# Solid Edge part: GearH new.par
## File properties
Author: vinurabandara
Template: iso metric part.par
Last saved by: Nimesh.N
Revision: 27
Application: Solid Edge
Density: 7250.000 kg/m^3
Accuracy: 0.990
Username: Nimesh.N
Material: Iron:0.6025 , EN-GJL-250
Face Style: Gray
Fill Style: ANSI31(Iron)
Grouping: Iron\Gray Cast Iron
LibraryName: Materials-DIN
Coef. of Thermal Exp: 1.05e-05
Thermal Conductivity: 58.0
Specific Heat: 460.0
Modulus of Elasticity: 120000003072.0
Poisson's Ratio: 0.26
Yield Stress: 165593984.0
Ultimate Stress: 250000000.0
Elongation: 0.0
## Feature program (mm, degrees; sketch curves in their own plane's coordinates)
sketch for "unnamed Protrusion 1" plane through (0, 0, 0) normal (0, 0, 1) x-axis (1, 0, 0)
  circle centre (0, 0) radius 200
extrude "unnamed Protrusion 1" add finite 130 along -normal
sketch used by "unnamed Cutout 1" plane through (0, 0, 0) normal (0, 0, 1) x-axis (1, 0, 0)
  line (0, 0) -> (-16.5159, 199.3169)
  line (0, 0) -> (-13.768, 199.5255)
  line (0, 0) -> (-34.7296, 196.9616)
  line (-3.6684, 177.4621) -> (3.6684, 177.4621)
  arc centre (-62.147, 164.0365) radius 60 from (-13.768, 199.5255) to (-3.6684, 177.4621) cw
  arc centre (62.147, 164.0365) radius 60 from (13.768, 199.5255) to (3.6684, 177.4621) ccw
extrude "unnamed Cutout 1" cut through along -normal
pattern "unnamed Pattern 1" of "unnamed Cutout 1"
pattern "unnamed Pattern 2"
sketch for "unnamed Cutout 2" plane through (0, 0, 0) normal (0, 0, 1) x-axis (0.789141, 0.614213, 0)
extrude "unnamed Cutout 2" cut through along -normal
sketch for "unnamed Cutout 3" plane through (0, 0, 0) normal (0, 0, 1) x-axis (0.789141, 0.614213, 0)
  line (-8.125, 39.8042) -> (-8.125, 31.468)
  line (8.125, 39.8042) -> (8.125, 31.468)
extrude "unnamed Cutout 3" cut through along -normal
pattern "unnamed Pattern 3" of "unnamed Cutout 3"
pattern "unnamed Pattern 4"
sketch used by "unnamed Protrusion 2" plane through (0, 0, 0) normal (0, 0, 1) x-axis (1, 0, 0)
  circle centre (0, 0) radius 200
extrude "unnamed Protrusion 2" add finite
sketch for "unnamed Protrusion 3" #1 plane through (0, 0, 0) normal (0, 0, 1) x-axis (0.789141, 0.614213, 0)
sketch for "unnamed Protrusion 3" #2 plane through (0, 0, 0) normal (0, 0, 1) x-axis (0.789141, 0.614213, 0)
extrude "unnamed Protrusion 3" add finite
sketch for "unnamed Protrusion 4" plane through (0, 0, 0) normal (0, 0, 1) x-axis (0.789141, 0.614213, 0)
extrude "unnamed Protrusion 4" add finite
sketch for "unnamed Protrusion 5" plane through (0, 0, 0) normal (0, 0, 1) x-axis (0.789141, 0.614213, 0)
  circle centre (0, 0) radius 150.1838
extrude "unnamed Protrusion 5" add finite
sketch for "unnamed Protrusion 6" plane through (0, 0, 0) normal (0, 0, 1) x-axis (0.789141, 0.614213, 0)
  circle centre (0, 0) radius 135.167
extrude "unnamed Protrusion 6" add finite
sketch for "unnamed Cutout 4" #1 plane through (0, 0, 0) normal (0, 0, 1) x-axis (0.789141, 0.614213, 0)
  circle centre (0, 0) radius 71
sketch for "unnamed Cutout 4" #2 plane through (0, 0, 0) normal (0, 0, 1) x-axis (0.789141, 0.614213, 0)
  circle centre (0, 0) radius 159.75
extrude "unnamed Cutout 4" cut finite 35 along -normal
mirror "unnamed Mirror 1" of "unnamed Cutout 4"
pattern "unnamed Pattern 5"
sketch for "unnamed Cutout 5" plane through (0, 0, -35) normal (0, 0, 1) x-axis (1, 0, 0)
extrude "unnamed Cutout 5" cut through along -normal
pattern "unnamed Pattern 6" of "unnamed Cutout 5"
pattern "unnamed Pattern 7"
fillet "unnamed Round 1"
fillet "Round_3" radius 10
sketch for "ExtrudedProtrusion_9" #1 plane through (0, 0, -130) normal (0, 0, -1) x-axis (0, 1, 0)
sketch for "ExtrudedProtrusion_9" #2 plane through (0, 0, -130) normal (0, 0, -1) x-axis (0, 1, 0)
extrude "ExtrudedProtrusion_9" add finite 20 along +normal
sketch for "ExtrudedCutout_24" #1 plane through (0, 0, -150) normal (0, 0, -1) x-axis (0, 1, 0)
sketch for "ExtrudedCutout_24" #2 plane through (0, 0, -150) normal (0, 0, -1) x-axis (0, 1, 0)
extrude "ExtrudedCutout_24" cut finite 10 along -normal
sketch for "ExtrudedProtrusion_10" #1 plane through (0, 0, -150) normal (0, 0, -1) x-axis (-1, 0, 0)
  circle centre (0, 0) radius 32.5
sketch for "ExtrudedProtrusion_10" #2 plane through (0, 0, -150) normal (0, 0, -1) x-axis (-1, 0, 0)
extrude "ExtrudedProtrusion_10" add finite 10 along +normal
fillet "Round_4" radius 2  Radii2 = 3 mm
Other named dimensions: "ExtrudedSurface_3": FiniteDepth = 130 mm
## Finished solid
Body 1: sheet body, 1 face, 2 edges, 0 vertices.
  Faces by surface: cylinder 1
  Edges by curve: circle 2
Body 2: solid body, 232 faces, 662 edges, 432 vertices.
  Faces by surface: cylinder 160, plane 70, torus 2
  Edges by curve: line 340, circle 322
Bounding box of the edges (mm; curved faces can reach further): 400.000 x 399.051 x 160.000, from (-200, -199.5255, -160) to (200, 199.5255, 0).
Cylindrical faces by radius (mm): R10 x16, R32.5 x8, R40.625 x8, R56 x1, R60 x76, R71 x3, R85.2 x4, R147.325 x4, R159.75 x2, R190 x1, R200 x38
Toroidal faces (ring radius, tube radius in mm): R68 r3 x1, R69 r2 x1
Planar faces by outward normal: +y 1, +z 4, -y 1, -z 4, oblique 60
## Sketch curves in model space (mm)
line (0, 0, 0) -> (-34.7296, 196.9616, 0)
line (0, 0, 0) -> (-16.5159, 199.3169, 0)
line (0, 0, 0) -> (4.1334, 199.9573, 0)
line (0, 0, 0) -> (-4.1334, 199.9573, 0)
arc centre (62.147, 164.0365, 0) radius 60 from (13.768, 199.5255, 0) through (7.5912, 189.0097, 0) to (3.6684, 177.4621, 0)
line (-3.6684, 177.4621, 0) -> (3.6684, 177.4621, 0)
arc centre (-62.147, 164.0365, 0) radius 60 from (-13.768, 199.5255, 0) through (-7.5912, 189.0097, 0) to (-3.6684, 177.4621, 0)
line (0, 0, 0) -> (-13.768, 199.5255, 0)
circle centre (0, 0, 0) radius 200
circle centre (0, 0, 0) radius 190
circle centre (0, 0, 0) radius 177.5
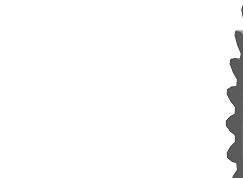
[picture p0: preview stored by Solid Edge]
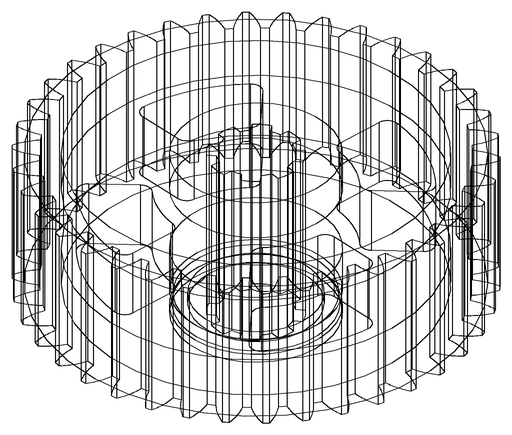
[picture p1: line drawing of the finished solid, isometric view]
